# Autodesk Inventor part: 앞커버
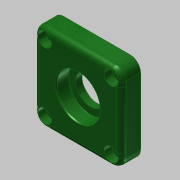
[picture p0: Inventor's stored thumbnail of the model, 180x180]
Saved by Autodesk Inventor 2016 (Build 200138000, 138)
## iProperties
Created: 2018-07
Part Number: 앞커버
Material: 알루미늄 6061
Document SubType Name: Modeling
Designer: mduedu
Density: 1 g/cm^3
Appearance: 매끄러움 - 짙은 산림 녹색
Author: mduedu
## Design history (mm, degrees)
sketch "스케치1"
  geometry: C1 r 16 at (0, 0); 1 further point
  constraints: 1 centre point, 1 coincident
  dimensions: "d0" = 32 diameter of C1
extrude "돌출1" new body sketch "스케치1" distance "d1" = 3; taper "d2" = 0 deg
sketch "스케치2"
  geometry: L1 (-25, -25)-(25, -25); L2 (25, -25)-(25, 25); L3 (25, 25)-(-25, 25); L4 (-25, 25)-(-25, -25); L5 (-25, -25)-(25, 25); L6 (25, -25)-(-25, 25); 1 further point
  constraints: 12 end point, 2 midpoint, 2 parallel, 1 horizontal, 1 perpendicular
  dimensions: "d3" = 50 distance of L3.end L2.end; "d4" = 50 distance of L2.end L1.end
extrude "돌출2" join sketch "스케치2" distance "d5" = 11; taper "d6" = 0 deg
hole "구멍1" diameter "d9" = 25; stored, may be unused: countersink angle "d13" = 90 deg, drill point angle "d15" = 0 deg; dims "d7" = 10, "d8" = 10, "d10" = 6, "d11" = 4, "d12" = 2, "d14" = 3
sketch "스케치3"
  geometry: C1 r 12.5 at (0, 0); 1 further point
  constraints: 1 centre point, 1 coincident
  dimensions: "d16" = 25 diameter of C1
extrude "돌출3" cut sketch "스케치3" distance "d17" = 7.3; taper "d18" = 0 deg
sketch "스케치4"
  geometry: C1 r 8.5 at (0, 0); 1 further point
  constraints: 1 centre point, 1 coincident
  dimensions: "d19" = 17 diameter of C1
extrude "돌출4" cut sketch "스케치4" stored distance "d20" = 7.3; taper "d21" = 0 deg
chamfer "모따기1" distance "d22" = 0.7; stored, may be unused: second distance "d23" = 2, angle "d24" = 30 deg
fillet "모깎기1" dims "d25" = 0.3
fillet "모깎기2" dims "d26" = 3
fillet "모깎기3" dims "d27" = 6
sketch "스케치5"
  geometry: L1 (25, -19)-(25, 19) reference; L2 (19, 25)-(-19, 25) reference; L3 (-25, 19)-(-25, -19) reference; L4 (-19, -25)-(19, -25) reference; C1 r 12.904 at (0, 0) reference; A1 r 6 centre (19, -19) between (19, -25) and (25, -19) reference; A2 r 6 centre (19, 19) between (25, 19) and (19, 25) reference; A3 r 6 centre (-19, 19) between (-19, 25) and (-25, 19) reference; A4 r 6 centre (-19, -19) between (-25, -19) and (-19, -25) reference; 5 further points
  constraints: 4 coincident
hole "구멍2" sketch "스케치5" at (-19, 19), (19, 19), (19, -19), (-19, -19) diameter "d28" = 4.5; stored, may be unused: countersink angle "d32" = 90 deg, drill point angle "d34" = 0 deg; dims "d29" = 6, "d30" = 8, "d31" = 4.6, "d33" = 3
fillet "모깎기4" dims "d35" = 3
chamfer "모따기2" distance "d36" = 1; stored, may be unused: second distance "d37" = 2, angle "d38" = 45 deg
node "솔리드1"
node "투영된 루프1"
